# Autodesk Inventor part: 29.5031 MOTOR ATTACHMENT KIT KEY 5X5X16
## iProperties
Created: 2007-07
Part Number: 29.5031 MOTOR ATTACHMENT KIT KEY 5X5X16
Material: Steel
Document SubType Name: Modeling
Designer: Andy Moles
Mass: 2.92944 g
Surface Area: 3.3781 cm^2
Volume: 0.373177 cm^3
Density: 7.85 g/cm^3
Author: Andy Moles
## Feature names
1. Extrusion1
